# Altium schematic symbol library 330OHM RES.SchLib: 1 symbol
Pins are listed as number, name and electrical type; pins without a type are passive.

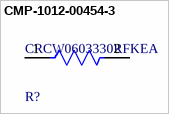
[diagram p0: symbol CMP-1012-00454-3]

## CMP-1012-00454-3
designator R?, comment CRCW0603330RFKEA
RES Thick Film, 330Ω, 1%, 0.1W, 100ppm/°C, 0603; Voltage Rating: 75V; Max Power Dissipation: 100mW; Resistance: 330R
footprint FP-CRCW0603-e3-MFG
footprint FP-CRCW0603-e3-IPC_A
footprint FP-CRCW0603-e3-IPC_B
footprint FP-CRCW0603-e3-IPC_C
pins: 1, 2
